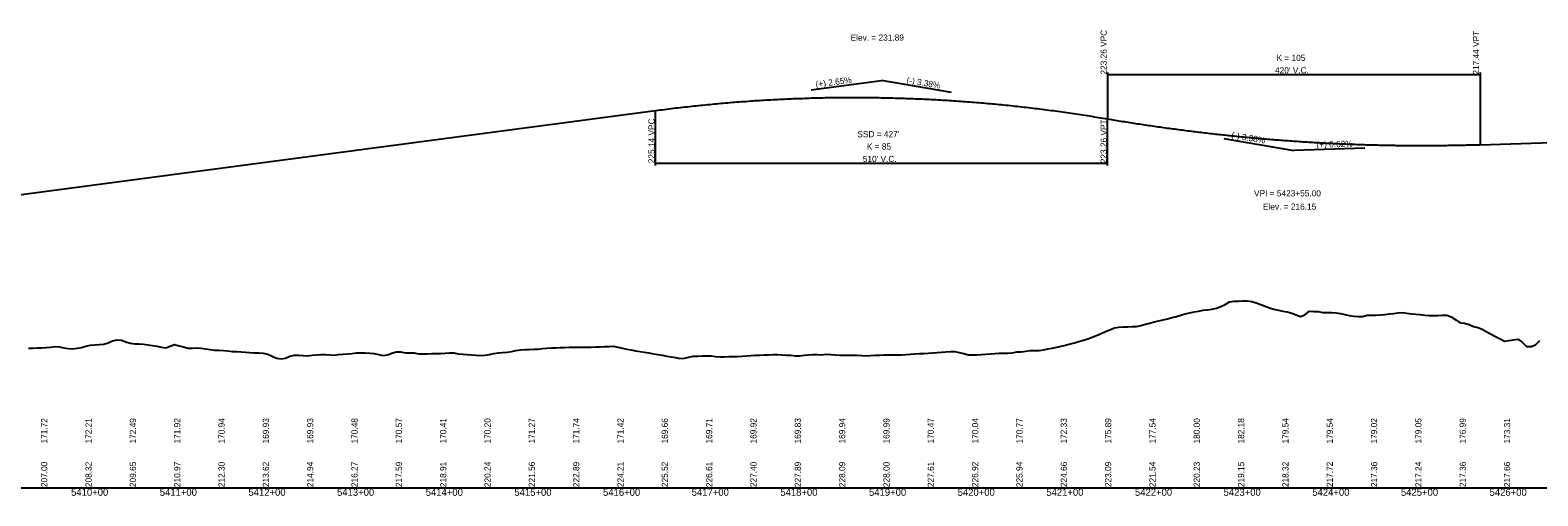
# Model space of a CAD drawing. Extents: x 1838386 to 1955906, y 719739 to 834437.
# Drawn here: x 1878884 to 1880584, y 775980 to 776506 of the extents above; entities that cross this region are included whole.
import ezdxf

# ---------------------------------------------------------------- set-up
doc = ezdxf.new("R2010")
doc.units = 0
for name, color, linetype in [('RD_DDB_GradeTX', 7, 'Continuous'), ('RD_DDB_Profile_EX', 7, 'Continuous'), ('RD_DDB_Profile_Lbl', 7, 'Continuous'), ('RD_DDB_Profile_PR', 7, 'Continuous'), ('RD_DDB_StaTX', 7, 'Continuous'), ('RD_DDB_StripGrade', 7, 'Continuous'), ('RD_DDB_VCLbl', 7, 'Continuous'), ('RD_GPK_Profile_Cell', 7, 'Continuous')]:
    doc.layers.add(name, color=color, linetype=linetype)

msp = doc.modelspace()

# ---------------------------------------------------------------- linework, layer by layer
at = {"layer": 'RD_DDB_GradeTX'}
for p, q in [((1879764.7, 776438.1), (1879844, 776448.6)), ((1879922.9, 776435.2), (1879844, 776448.6)), ((1880230.1, 776383.2), (1880309, 776369.9)), ((1880389, 776372.3), (1880309, 776369.9))]:
    msp.add_line(p, q, dxfattribs=at)
at = {"layer": 'RD_DDB_Profile_EX'}
for points in [[(1880181.6, 776183.8), (1880186.6, 776185.3), (1880191.6, 776186.4), (1880196.6, 776187.5), (1880201.6, 776188.6), (1880206.6, 776189.7), (1880211.6, 776189.8), (1880216.6, 776190.8), (1880221.6, 776191.9), (1880226.6, 776193.6), (1880231.6, 776195.8), (1880236.6, 776198.9), (1880241.6, 776199.7), (1880246.6, 776199.8), (1880251.6, 776200), (1880256.6, 776200.1), (1880261.6, 776199.4), (1880266.6, 776197.7), (1880271.6, 776195.9), (1880276.6, 776194), (1880281.6, 776192.3), (1880286.6, 776190.7), (1880291.6, 776189.5), (1880296.6, 776188.4), (1880301.6, 776187.6), (1880306.6, 776186), (1880311.6, 776184.3), (1880316.6, 776182.6), (1880321.6, 776184.4), (1880326.6, 776188.3), (1880331.6, 776188.2), (1880336.6, 776187.9), (1880341.6, 776186.8), (1880346.6, 776187.1), (1880351.6, 776187.1), (1880356.6, 776186.6), (1880361.6, 776185.7), (1880366.6, 776184.6), (1880371.6, 776183.6), (1880376.6, 776182.9), (1880381.6, 776182.5), (1880386.6, 776182.6), (1880391.6, 776183.9), (1880396.6, 776183.9), (1880401.6, 776184.1), (1880406.6, 776184.3), (1880411.6, 776184.8), (1880416.6, 776185.4), (1880421.6, 776185.8), (1880426.6, 776186.5), (1880431.6, 776186.8), (1880436.6, 776186), (1880441.6, 776185.6), (1880446.6, 776185.2), (1880451.6, 776184.7), (1880456.6, 776184.1), (1880461.6, 776183.7), (1880466.6, 776183.4), (1880471.6, 776183.6), (1880476.6, 776184.1), (1880481.6, 776184), (1880486.6, 776181.9), (1880491.6, 776178.6), (1880496.6, 776175.2), (1880501.6, 776174.8), (1880506.6, 776173.3), (1880511.6, 776171.3), (1880516.6, 776170.1), (1880521.6, 776168.1), (1880526.6, 776165.3), (1880531.6, 776162.6), (1880536.6, 776160), (1880541.6, 776157.4), (1880546.6, 776154.6), (1880551.6, 776155.3), (1880556.6, 776156.1), (1880561.6, 776156.7), (1880566.6, 776153.4), (1880571.6, 776148.5), (1880576.6, 776148.5), (1880581.6, 776150.3), (1880586.6, 776155.5)], [(1879681.6, 776137.4), (1879686.6, 776137.7), (1879691.6, 776138), (1879696.6, 776138.3), (1879701.6, 776138.6), (1879706.6, 776138.9), (1879711.6, 776139.1), (1879716.6, 776139.3), (1879721.6, 776139.4), (1879726.6, 776139.6), (1879731.6, 776139.3), (1879736.6, 776138.9), (1879741.6, 776138.6), (1879746.6, 776138.2), (1879751.6, 776138), (1879756.6, 776138.6), (1879761.6, 776139.1), (1879766.6, 776139.4), (1879771.6, 776139.5), (1879776.6, 776139.3), (1879781.6, 776139.9), (1879786.6, 776139.7), (1879791.6, 776139.1), (1879796.6, 776138.9), (1879801.6, 776138.8), (1879806.6, 776138.8), (1879811.6, 776138.8), (1879816.6, 776138.9), (1879821.6, 776138.5), (1879826.6, 776138.1), (1879831.6, 776138.4), (1879836.6, 776138.7), (1879841.6, 776138.9), (1879846.6, 776139), (1879851.6, 776139.1), (1879856.6, 776139.1), (1879861.6, 776139.2), (1879866.6, 776139.2), (1879871.6, 776139.6), (1879876.6, 776140), (1879881.6, 776140.4), (1879886.6, 776140.5), (1879891.6, 776140.7), (1879896.6, 776140.9), (1879901.6, 776141.3), (1879906.6, 776141.7), (1879911.6, 776142.1), (1879916.6, 776142.5), (1879921.6, 776142.9), (1879926.6, 776143), (1879931.6, 776141.8), (1879936.6, 776140.5), (1879941.6, 776139.3), (1879946.6, 776139), (1879951.6, 776139.2), (1879956.6, 776139.5), (1879961.6, 776139.9), (1879966.6, 776140.2), (1879971.6, 776140.6), (1879976.6, 776140.9), (1879981.6, 776140.9), (1879986.6, 776141), (1879991.6, 776141.6), (1879996.6, 776142.5), (1880001.6, 776142.7), (1880006.6, 776143.3), (1880011.6, 776144.1), (1880016.6, 776144), (1880021.6, 776144), (1880026.6, 776144.9), (1880031.6, 776145.8), (1880036.6, 776146.8), (1880041.6, 776147.8), (1880046.6, 776148.9), (1880051.6, 776150.2), (1880056.6, 776151.5), (1880061.6, 776152.7), (1880066.6, 776154.2), (1880071.6, 776155.7), (1880076.6, 776157.2), (1880081.6, 776159.1), (1880086.6, 776161.1), (1880091.6, 776163.2), (1880096.6, 776165.4), (1880101.6, 776167.5), (1880106.6, 776169.7), (1880111.6, 776170.5), (1880116.6, 776170.7), (1880121.6, 776170.9), (1880126.6, 776171.1), (1880131.6, 776171.3), (1880136.6, 776172.3), (1880141.6, 776173.7), (1880146.6, 776175), (1880151.6, 776176.3), (1880156.6, 776177.5), (1880161.6, 776178.7), (1880166.6, 776179.9), (1880171.6, 776181.1), (1880176.6, 776182.4), (1880181.6, 776183.8)], [(1878881.6, 776146.6), (1878886.6, 776146.6), (1878891.6, 776146.9), (1878896.6, 776147.2), (1878901.6, 776147.5), (1878906.6, 776148), (1878911.6, 776148.6), (1878916.6, 776148.1), (1878921.6, 776147), (1878926.6, 776146.4), (1878931.6, 776146.1), (1878936.6, 776146.5), (1878941.6, 776147.6), (1878946.6, 776149), (1878951.6, 776150), (1878956.6, 776150.4), (1878961.6, 776150.8), (1878966.6, 776151.2), (1878971.6, 776152.7), (1878976.6, 776154.8), (1878981.6, 776155.9), (1878986.6, 776155.7), (1878991.6, 776153.7), (1878996.6, 776152.3), (1879001.6, 776151.7), (1879006.6, 776151.4), (1879011.6, 776151.2), (1879016.6, 776150.6), (1879021.6, 776149.6), (1879026.6, 776148.8), (1879031.6, 776147.9), (1879036.6, 776147), (1879041.6, 776149.1), (1879046.6, 776150.7), (1879051.6, 776149.3), (1879056.6, 776148.1), (1879061.6, 776146.8), (1879066.6, 776146.7), (1879071.6, 776146.9), (1879076.6, 776146.6), (1879081.6, 776145.8), (1879086.6, 776145.1), (1879091.6, 776144.5), (1879096.6, 776144.3), (1879101.6, 776144), (1879106.6, 776143.7), (1879111.6, 776143.1), (1879116.6, 776142.9), (1879121.6, 776142.4), (1879126.6, 776142.1), (1879131.6, 776141.8), (1879136.6, 776141.5), (1879141.6, 776141.4), (1879146.6, 776141.1), (1879151.6, 776139.8), (1879156.6, 776137.8), (1879161.6, 776135.5), (1879166.6, 776134.8), (1879171.6, 776135.5), (1879176.6, 776137.5), (1879181.6, 776138.9)], [(1879181.6, 776138.9), (1879186.6, 776138.7), (1879191.6, 776138.5), (1879196.6, 776138.2), (1879201.6, 776138.6), (1879206.6, 776139), (1879211.6, 776139.5), (1879216.6, 776139.6), (1879221.6, 776139.1), (1879226.6, 776138.6), (1879231.6, 776139.4), (1879236.6, 776140.1), (1879241.6, 776140.3), (1879246.6, 776140.8), (1879251.6, 776141.5), (1879256.6, 776141.6), (1879261.6, 776141.4), (1879266.6, 776141.1), (1879271.6, 776140.5), (1879276.6, 776139.5), (1879281.6, 776138.4), (1879286.6, 776139.2), (1879291.6, 776140.9), (1879296.6, 776142.5), (1879301.6, 776142.4), (1879306.6, 776141.5), (1879311.6, 776141.5), (1879316.6, 776141.4), (1879321.6, 776140.4), (1879326.6, 776140.3), (1879331.6, 776140.3), (1879336.6, 776140.5), (1879341.6, 776140.8), (1879346.6, 776140.7), (1879351.6, 776141), (1879356.6, 776141.4), (1879361.6, 776141.3), (1879366.6, 776140.3), (1879371.6, 776139.8), (1879376.6, 776139.4), (1879381.6, 776139.1), (1879386.6, 776138.8), (1879391.6, 776138.5), (1879396.6, 776138.9), (1879401.6, 776139.6), (1879406.6, 776140.7), (1879411.6, 776141.3), (1879416.6, 776141.7), (1879421.6, 776142.2), (1879426.6, 776143.1), (1879431.6, 776144.1), (1879436.6, 776144.9), (1879441.6, 776145.2), (1879446.6, 776145.3), (1879451.6, 776145.4), (1879456.6, 776145.6), (1879461.6, 776146.2), (1879466.6, 776146.6), (1879471.6, 776146.9), (1879476.6, 776147.2), (1879481.6, 776147.5), (1879486.6, 776147.6), (1879491.6, 776147.7), (1879496.6, 776147.8), (1879501.6, 776147.8), (1879506.6, 776147.9), (1879511.6, 776147.8), (1879516.6, 776148), (1879521.6, 776148.1), (1879526.6, 776148.3), (1879531.6, 776148.5), (1879536.6, 776148.6), (1879541.6, 776148.8), (1879546.6, 776147.8), (1879551.6, 776146.7), (1879556.6, 776145.7), (1879561.6, 776144.7), (1879566.6, 776143.8), (1879571.6, 776143), (1879576.6, 776142.2), (1879581.6, 776141.3), (1879586.6, 776140.4), (1879591.6, 776139.6), (1879596.6, 776138.7), (1879601.6, 776137.8), (1879606.6, 776137), (1879611.6, 776136), (1879616.6, 776135), (1879621.6, 776135.4), (1879626.6, 776136.7), (1879631.6, 776137.5), (1879636.6, 776137.7), (1879641.6, 776137.9), (1879646.6, 776138.2), (1879651.6, 776138.1), (1879656.6, 776137.2), (1879661.6, 776136.8), (1879666.6, 776137), (1879671.6, 776137.1), (1879676.6, 776137.1), (1879681.6, 776137.4)]]:
    msp.add_lwpolyline(points, dxfattribs=at)
at = {"layer": 'RD_DDB_Profile_PR'}
for p, q in [((1878854, 776317.5), (1879589, 776414.8)), ((1880099, 776405.4), (1880099, 776405.4)), ((1880519, 776376.3), (1880834, 776386.1))]:
    msp.add_line(p, q, dxfattribs=at)
for points in [[(1879589, 776414.8), (1879599.2, 776416.1), (1879609.4, 776417.4), (1879619.6, 776418.6), (1879629.8, 776419.7), (1879640, 776420.8), (1879650.2, 776421.8), (1879660.4, 776422.8), (1879670.6, 776423.7), (1879680.8, 776424.5), (1879691, 776425.2), (1879701.2, 776426), (1879711.4, 776426.6), (1879721.6, 776427.2), (1879731.8, 776427.7), (1879742, 776428.2), (1879752.2, 776428.5), (1879762.4, 776428.9), (1879772.6, 776429.2), (1879782.8, 776429.4), (1879793, 776429.5), (1879803.2, 776429.6), (1879813.4, 776429.6), (1879823.6, 776429.6), (1879833.8, 776429.5), (1879844, 776429.3), (1879854.2, 776429.1), (1879864.4, 776428.8), (1879874.6, 776428.5), (1879884.8, 776428.1), (1879895, 776427.6), (1879905.2, 776427.1), (1879915.4, 776426.5), (1879925.6, 776425.9), (1879935.8, 776425.2), (1879946, 776424.4), (1879956.2, 776423.6), (1879966.4, 776422.7), (1879976.6, 776421.7), (1879986.8, 776420.7), (1879997, 776419.6), (1880007.2, 776418.5), (1880017.4, 776417.3), (1880027.6, 776416), (1880037.8, 776414.7), (1880048, 776413.3), (1880058.2, 776411.8), (1880068.4, 776410.3), (1880078.6, 776408.7), (1880088.8, 776407.1), (1880099, 776405.4)], [(1880099, 776405.4), (1880107.4, 776404), (1880115.8, 776402.6), (1880124.2, 776401.3), (1880132.6, 776400), (1880141, 776398.7), (1880149.4, 776397.5), (1880157.8, 776396.3), (1880166.2, 776395.1), (1880174.6, 776394), (1880183, 776392.9), (1880191.4, 776391.8), (1880199.8, 776390.8), (1880208.2, 776389.8), (1880216.6, 776388.8), (1880225, 776387.9), (1880233.4, 776387), (1880241.8, 776386.1), (1880250.2, 776385.3), (1880258.6, 776384.5), (1880267, 776383.7), (1880275.4, 776383), (1880283.8, 776382.3), (1880292.2, 776381.6), (1880300.6, 776381), (1880309, 776380.4), (1880317.4, 776379.8), (1880325.8, 776379.3), (1880334.2, 776378.8), (1880342.6, 776378.3), (1880351, 776377.9), (1880359.4, 776377.5), (1880367.8, 776377.1), (1880376.2, 776376.8), (1880384.6, 776376.5), (1880393, 776376.2), (1880401.4, 776376), (1880409.8, 776375.8), (1880418.2, 776375.7), (1880426.6, 776375.5), (1880435, 776375.4), (1880443.4, 776375.4), (1880451.8, 776375.4), (1880460.2, 776375.4), (1880468.6, 776375.4), (1880477, 776375.5), (1880485.4, 776375.6), (1880493.8, 776375.7), (1880502.2, 776375.9), (1880510.6, 776376.1), (1880519, 776376.3)]]:
    msp.add_spline(points, degree=3, dxfattribs=at)
at = {"layer": 'RD_DDB_VCLbl'}
for p, q in [((1880099, 776457.9), (1880099, 776405.4)), ((1880099, 776455.4), (1880519, 776455.4)), ((1880519, 776457.9), (1880519, 776376.3)), ((1879589, 776352.9), (1879589, 776414.8)), ((1880099, 776352.9), (1880099, 776405.4)), ((1879589, 776355.4), (1880099, 776355.4))]:
    msp.add_line(p, q, dxfattribs=at)
at = {"layer": 'RD_GPK_Profile_Cell'}
msp.add_line((1877681.6, 775989.1), (1883481.6, 775989.1), dxfattribs=at)

# ---------------------------------------------------------------- texts
at = {"layer": 'RD_DDB_GradeTX'}
for s, rotation, p in [('(+) 2.65%', 7.5405, (1879770.1, 776440.8)), ('(-) 3.38%', 350.3942, (1879871.7, 776445.9)), ('(-) 3.38%', 350.3942, (1880238.1, 776383.9)), ('(+) 0.62%', 1.7643, (1880334.6, 776372.7))]:
    msp.add_text(s, height=7, rotation=rotation, dxfattribs=at).set_placement(p)
at = {"layer": 'RD_DDB_Profile_Lbl'}
for s, p in [('Elev. = 231.89', (1879809.1, 776493.6)), ('VPI = 5423+55.00', (1880264.1, 776317.9)), ('Elev. = 216.15', (1880274.2, 776302.9))]:
    msp.add_text(s, height=7, dxfattribs=at).set_placement(p)
at = {"layer": 'RD_DDB_StaTX'}
for s, p in [('5410+00', (1878929.8, 775980.1)), ('5411+00', (1879029.8, 775980.1)), ('5412+00', (1879129.8, 775980.1)), ('5413+00', (1879229.8, 775980.1)), ('5414+00', (1879329.8, 775980.1)), ('5415+00', (1879429.8, 775980.1)), ('5416+00', (1879529.8, 775980.1)), ('5417+00', (1879629.8, 775980.1)), ('5418+00', (1879729.8, 775980.1)), ('5419+00', (1879829.8, 775980.1)), ('5420+00', (1879929.8, 775980.1)), ('5421+00', (1880029.8, 775980.1)), ('5422+00', (1880129.8, 775980.1)), ('5423+00', (1880229.8, 775980.1)), ('5424+00', (1880329.8, 775980.1)), ('5425+00', (1880429.8, 775980.1)), ('5426+00', (1880529.8, 775980.1))]:
    msp.add_text(s, height=8, dxfattribs=at).set_placement(p)
at = {"layer": 'RD_DDB_StripGrade'}
for s, p in [('223.26 VPC', (1880098, 776455.4)), ('217.44 VPT', (1880518, 776455.4)), ('225.14 VPC', (1879588, 776355.4)), ('223.26 VPT', (1880098, 776355.4)), ('171.72', (1878903, 776039.1)), ('172.21', (1878953, 776039.1)), ('172.49', (1879003, 776039.1)), ('171.92', (1879053, 776039.1)), ('170.94', (1879103, 776039.1)), ('169.93', (1879153, 776039.1)), ('169.93', (1879203, 776039.1)), ('170.48', (1879253, 776039.1)), ('170.57', (1879303, 776039.1)), ('170.41', (1879353, 776039.1)), ('170.20', (1879403, 776039.1)), ('171.27', (1879453, 776039.1)), ('171.74', (1879503, 776039.1)), ('171.42', (1879553, 776039.1)), ('169.66', (1879603, 776039.1)), ('169.71', (1879653, 776039.1)), ('169.92', (1879703, 776039.1)), ('169.83', (1879753, 776039.1)), ('169.94', (1879803, 776039.1)), ('169.99', (1879853, 776039.1)), ('170.47', (1879903, 776039.1)), ('170.04', (1879953, 776039.1)), ('170.77', (1880003, 776039.1)), ('172.33', (1880053, 776039.1)), ('175.89', (1880103, 776039.1)), ('177.54', (1880153, 776039.1)), ('180.00', (1880203, 776039.1)), ('182.18', (1880253, 776039.1)), ('179.54', (1880303, 776039.1)), ('179.54', (1880353, 776039.1)), ('179.02', (1880403, 776039.1)), ('179.05', (1880453, 776039.1)), ('176.99', (1880503, 776039.1)), ('173.31', (1880553, 776039.1)), ('207.00', (1878903, 775989.9)), ('208.32', (1878953, 775989.9)), ('209.65', (1879003, 775989.9)), ('210.97', (1879053, 775989.9)), ('212.30', (1879103, 775989.9)), ('213.62', (1879153, 775989.9)), ('214.94', (1879203, 775989.9)), ('216.27', (1879253, 775989.9)), ('217.59', (1879303, 775989.9)), ('218.91', (1879353, 775989.9)), ('220.24', (1879403, 775989.9)), ('221.56', (1879453, 775989.9)), ('222.89', (1879503, 775989.9)), ('224.21', (1879553, 775989.9)), ('225.52', (1879603, 775989.9)), ('226.61', (1879653, 775989.9)), ('227.40', (1879703, 775989.9)), ('227.89', (1879753, 775989.9)), ('228.09', (1879803, 775989.9)), ('228.00', (1879853, 775989.9)), ('227.61', (1879903, 775989.9)), ('226.92', (1879953, 775989.9)), ('225.94', (1880003, 775989.9)), ('224.66', (1880053, 775989.9)), ('223.09', (1880103, 775989.9)), ('221.54', (1880153, 775989.9)), ('220.23', (1880203, 775989.9)), ('219.15', (1880253, 775989.9)), ('218.32', (1880303, 775989.9)), ('217.72', (1880353, 775989.9)), ('217.36', (1880403, 775989.9)), ('217.24', (1880453, 775989.9)), ('217.36', (1880503, 775989.9)), ('217.66', (1880553, 775989.9))]:
    msp.add_text(s, height=7, rotation=90, dxfattribs=at).set_placement(p)
at = {"layer": 'RD_DDB_VCLbl'}
for s, p in [('K = 105', (1880289.5, 776470.7)), ("420' V.C.", (1880287.8, 776456.7)), ("SSD = 427'", (1879816.7, 776384.7)), ("510' V.C.", (1879822.8, 776356.7)), ('K = 85', (1879827.4, 776370.7))]:
    msp.add_text(s, height=7, dxfattribs=at).set_placement(p)

doc.saveas('drawing.dxf')
